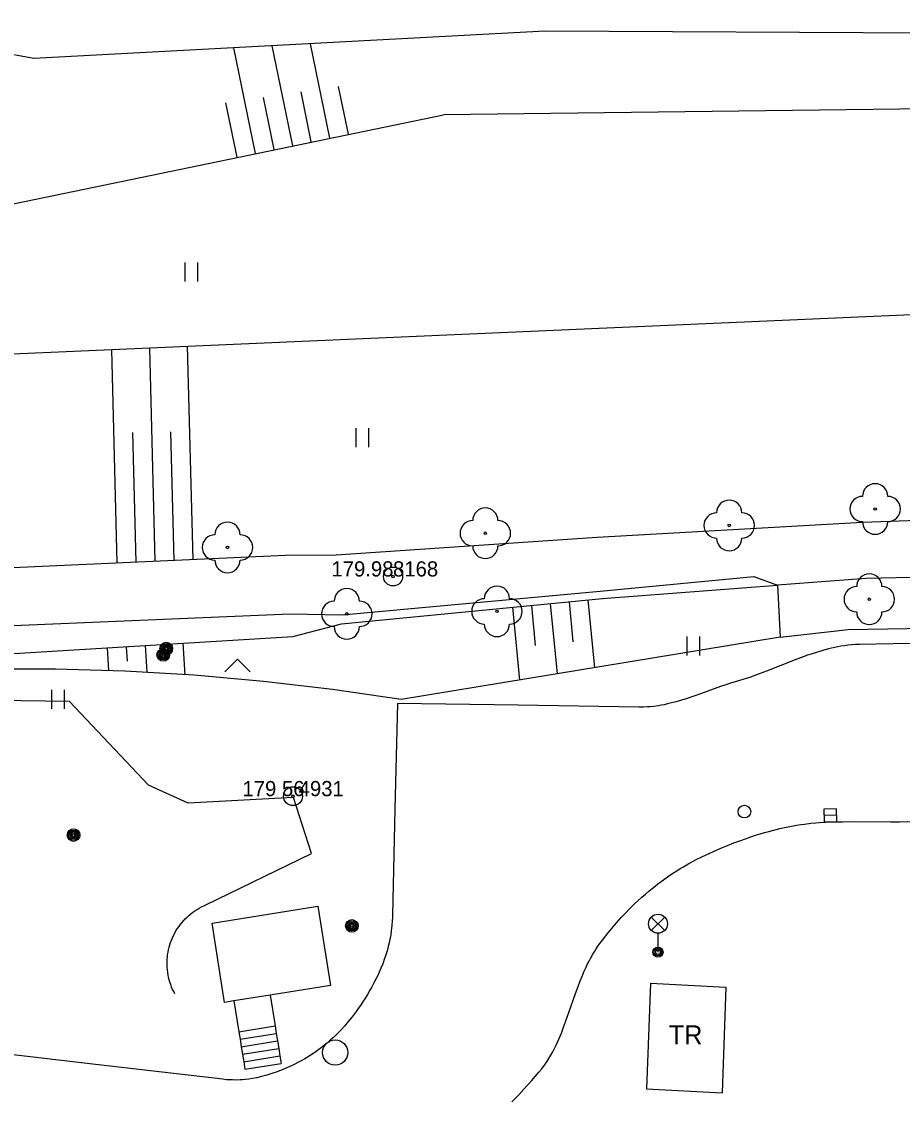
# Model space of a CAD drawing. Extents: x -538441 to -536770, y -1181008 to -1179809.
# Drawn here: x -537430.73 to -537395.89, y -1180815.56 to -1180772.89 of the extents above; entities that cross this region are included whole.
import ezdxf

# ---------------------------------------------------------------- set-up
doc = ezdxf.new("R2010")
doc.units = 0
for name, color, linetype in [('Vrstva 10', 7, 'Continuous'), ('Vrstva 11', 7, 'Continuous'), ('Vrstva 14', 7, 'Continuous'), ('Vrstva 15', 7, 'Continuous'), ('Vrstva 21', 7, 'Continuous'), ('Vrstva 22', 7, 'Continuous'), ('Vrstva 23', 7, 'Continuous'), ('Vrstva 25', 7, 'Continuous'), ('Vrstva 27', 7, 'Continuous'), ('Vrstva 28', 7, 'Continuous'), ('Vrstva 33', 7, 'Continuous'), ('Vrstva 36', 7, 'Continuous'), ('Vrstva 41', 7, 'Continuous'), ('Vrstva 5', 7, 'Continuous')]:
    doc.layers.add(name, color=color, linetype=linetype)

msp = doc.modelspace()

# ---------------------------------------------------------------- linework, layer by layer
at = {"layer": 'Vrstva 10'}
msp.add_line((-537392.278, -1180797.422), (-537397.59, -1180797.53), dxfattribs=at)
for points in [[(-537397.59, -1180797.53), (-537397.747, -1180797.536), (-537397.898, -1180797.546), (-537398.044, -1180797.561), (-537398.184, -1180797.579), (-537398.32, -1180797.6), (-537398.451, -1180797.624), (-537398.577, -1180797.649), (-537398.699, -1180797.676), (-537398.817, -1180797.705), (-537399.044, -1180797.766), (-537399.256, -1180797.829), (-537399.454, -1180797.893), (-537399.639, -1180797.956), (-537399.813, -1180798.018), (-537400.137, -1180798.14), (-537401.268, -1180798.588), (-537401.552, -1180798.695), (-537401.765, -1180798.773), (-537401.926, -1180798.829), (-537402.167, -1180798.908), (-537402.41, -1180798.98), (-537402.652, -1180799.052), (-537402.878, -1180799.125), (-537403.089, -1180799.197), (-537403.486, -1180799.338), (-537403.832, -1180799.464), (-537404.136, -1180799.571), (-537404.402, -1180799.661), (-537404.636, -1180799.735), (-537404.84, -1180799.795), (-537405.02, -1180799.843), (-537405.178, -1180799.881), (-537405.317, -1180799.911), (-537405.438, -1180799.934), (-537405.545, -1180799.953), (-537405.732, -1180799.979), (-537405.873, -1180799.994), (-537405.98, -1180800.002), (-537406.139, -1180800.009), (-537406.3, -1180800.01)], [(-537415.87, -1180799.86), (-537415.965, -1180804.05), (-537416.06, -1180808.24), (-537416.064, -1180808.349), (-537416.069, -1180808.454), (-537416.085, -1180808.656), (-537416.108, -1180808.843), (-537416.134, -1180809.018), (-537416.164, -1180809.182), (-537416.197, -1180809.334), (-537416.231, -1180809.476), (-537416.266, -1180809.608), (-537416.303, -1180809.732)], [(-537406.3, -1180800.01), (-537411.085, -1180799.935), (-537415.87, -1180799.86)], [(-537403.072, -1180805.589), (-537402.805, -1180805.478), (-537402.555, -1180805.379), (-537402.32, -1180805.29), (-537402.099, -1180805.211), (-537401.892, -1180805.14), (-537401.697, -1180805.076), (-537401.514, -1180805.019), (-537401.342, -1180804.969), (-537401.181, -1180804.924), (-537401.03, -1180804.884), (-537400.745, -1180804.814), (-537400.495, -1180804.759), (-537400.276, -1180804.716), (-537400.084, -1180804.682), (-537399.915, -1180804.655), (-537399.767, -1180804.634), (-537399.507, -1180804.603), (-537399.311, -1180804.583), (-537399.164, -1180804.572), (-537398.942, -1180804.558), (-537398.72, -1180804.55), (-537398.244, -1180804.541), (-537397.827, -1180804.538), (-537396.368, -1180804.54), (-537396.004, -1180804.539), (-537395.457, -1180804.534)], [(-537409.291, -1180812.672), (-537409.212, -1180812.457), (-537409.068, -1180812.049), (-537408.82, -1180811.33), (-537408.722, -1180811.061), (-537408.633, -1180810.828), (-537408.551, -1180810.625), (-537408.476, -1180810.45), (-537408.407, -1180810.298), (-537408.343, -1180810.166), (-537408.286, -1180810.052), (-537408.233, -1180809.953), (-537408.137, -1180809.782), (-537408.061, -1180809.656), (-537408.002, -1180809.563), (-537407.909, -1180809.425), (-537407.81, -1180809.29), (-537407.705, -1180809.153), (-537407.602, -1180809.021), (-537407.398, -1180808.772), (-537407.203, -1180808.543), (-537407.016, -1180808.334), (-537406.837, -1180808.143), (-537406.667, -1180807.968), (-537406.504, -1180807.807), (-537406.348, -1180807.66), (-537406.2, -1180807.525), (-537406.058, -1180807.401), (-537405.924, -1180807.286), (-537405.796, -1180807.181), (-537405.675, -1180807.085), (-537405.56, -1180806.996), (-537405.341, -1180806.833), (-537405.145, -1180806.695), (-537404.97, -1180806.578), (-537404.815, -1180806.478), (-537404.677, -1180806.392), (-537404.555, -1180806.319), (-537404.338, -1180806.195), (-537404.172, -1180806.105), (-537404.046, -1180806.039), (-537403.855, -1180805.943), (-537403.66, -1180805.85), (-537403.357, -1180805.713), (-537403.072, -1180805.589)], [(-537416.303, -1180809.732), (-537416.339, -1180809.847), (-537416.375, -1180809.955), (-537416.449, -1180810.157), (-537416.519, -1180810.333), (-537416.586, -1180810.486), (-537416.647, -1180810.62), (-537416.703, -1180810.737), (-537416.807, -1180810.941), (-537416.889, -1180811.094), (-537416.954, -1180811.208), (-537417.054, -1180811.379), (-537417.16, -1180811.55), (-537417.246, -1180811.683), (-537417.33, -1180811.809), (-537417.414, -1180811.929), (-537417.496, -1180812.043), (-537417.577, -1180812.152), (-537417.656, -1180812.255), (-537417.734, -1180812.353), (-537417.811, -1180812.446), (-537417.964, -1180812.622), (-537418.11, -1180812.781), (-537418.251, -1180812.925), (-537418.386, -1180813.056), (-537418.516, -1180813.174), (-537418.639, -1180813.282), (-537418.757, -1180813.379), (-537418.87, -1180813.468), (-537418.977, -1180813.549), (-537419.079, -1180813.623), (-537419.176, -1180813.691), (-537419.362, -1180813.812), (-537419.527, -1180813.914), (-537419.675, -1180813.999), (-537419.807, -1180814.07), (-537419.924, -1180814.13), (-537420.028, -1180814.181), (-537420.213, -1180814.266), (-537420.354, -1180814.326), (-537420.461, -1180814.369), (-537420.624, -1180814.431), (-537420.79, -1180814.49), (-537420.914, -1180814.531), (-537421.031, -1180814.566), (-537421.14, -1180814.596), (-537421.243, -1180814.622), (-537421.435, -1180814.666), (-537421.603, -1180814.697), (-537421.75, -1180814.719), (-537421.879, -1180814.734), (-537421.991, -1180814.744), (-537422.09, -1180814.751), (-537422.262, -1180814.757), (-537422.392, -1180814.756), (-537422.489, -1180814.753), (-537422.634, -1180814.744), (-537422.78, -1180814.73)], [(-537409.593, -1180813.384), (-537409.535, -1180813.26), (-537409.481, -1180813.138), (-537409.38, -1180812.899), (-537409.291, -1180812.672)], [(-537422.78, -1180814.73), (-537427.695, -1180814.155), (-537432.314, -1180813.615)], [(-537411.337, -1180815.626), (-537411.064, -1180815.337), (-537410.862, -1180815.119), (-537410.563, -1180814.787), (-537410.416, -1180814.619), (-537410.27, -1180814.45), (-537410.158, -1180814.312), (-537410.055, -1180814.175), (-537409.961, -1180814.039), (-537409.875, -1180813.904), (-537409.796, -1180813.771), (-537409.723, -1180813.64), (-537409.656, -1180813.511)], [(-537409.656, -1180813.511), (-537409.593, -1180813.384)]]:
    msp.add_lwpolyline(points, dxfattribs=at)
at = {"layer": 'Vrstva 11'}
for p, q in [((-537420.293, -1180794.008), (-537438.556, -1180794.829)), ((-537418.294, -1180793.996), (-537420.293, -1180794.008)), ((-537407.85, -1180795.415), (-537401.77, -1180794.843)), ((-537401.77, -1180794.843), (-537400.826, -1180795.182)), ((-537384.63, -1180794.687), (-537397.336, -1180794.914)), ((-537418.058, -1180796.359), (-537407.85, -1180795.415)), ((-537438.451, -1180797.087), (-537420.107, -1180796.322)), ((-537420.107, -1180796.322), (-537418.058, -1180796.359)), ((-537398.035, -1180796.942), (-537384.349, -1180796.71)), ((-537423.44, -1180807.83), (-537419.26, -1180805.8)), ((-537422.138, -1180812.847), (-537420.706, -1180812.618)), ((-537422.091, -1180813.144), (-537420.659, -1180812.915)), ((-537422.044, -1180813.44), (-537420.612, -1180813.211)), ((-537421.996, -1180813.736), (-537420.564, -1180813.507)), ((-537421.949, -1180814.032), (-537420.517, -1180813.803)), ((-537421.902, -1180814.329), (-537420.47, -1180814.1))]:
    msp.add_line(p, q, dxfattribs=at)
for points in [[(-537397.336, -1180794.914), (-537400.826, -1180795.182), (-537400.729, -1180797.245), (-537398.035, -1180796.942)], [(-537428.84, -1180799.78), (-537455.66, -1180799.41)], [(-537425.72, -1180803.1), (-537428.84, -1180799.78)], [(-537419.26, -1180805.8), (-537419.98, -1180803.58), (-537424.15, -1180803.8), (-537425.72, -1180803.1)], [(-537424.67, -1180811.35), (-537424.716, -1180811.261), (-537424.759, -1180811.171), (-537424.798, -1180811.079), (-537424.834, -1180810.985), (-537424.866, -1180810.89), (-537424.894, -1180810.794), (-537424.918, -1180810.696), (-537424.938, -1180810.598), (-537424.954, -1180810.499), (-537424.966, -1180810.4), (-537424.974, -1180810.3), (-537424.979, -1180810.2), (-537424.979, -1180810.1), (-537424.975, -1180810), (-537424.967, -1180809.9), (-537424.956, -1180809.801), (-537424.94, -1180809.702), (-537424.92, -1180809.603), (-537424.897, -1180809.506), (-537424.87, -1180809.41), (-537424.838, -1180809.315), (-537424.803, -1180809.221), (-537424.765, -1180809.128), (-537424.722, -1180809.038), (-537424.676, -1180808.949), (-537424.627, -1180808.861), (-537424.574, -1180808.776), (-537424.518, -1180808.694), (-537424.458, -1180808.613), (-537424.396, -1180808.535), (-537424.33, -1180808.459), (-537424.261, -1180808.386), (-537424.189, -1180808.316), (-537424.115, -1180808.249), (-537424.038, -1180808.185), (-537423.959, -1180808.124), (-537423.877, -1180808.066), (-537423.793, -1180808.012), (-537423.707, -1180807.961), (-537423.619, -1180807.913), (-537423.529, -1180807.869), (-537423.44, -1180807.83)], [(-537420.9, -1180811.401), (-537420.706, -1180812.618), (-537420.659, -1180812.915), (-537420.612, -1180813.211), (-537420.564, -1180813.507), (-537420.517, -1180813.803), (-537420.47, -1180814.1)], [(-537422.333, -1180811.63), (-537422.138, -1180812.847), (-537422.091, -1180813.144), (-537422.044, -1180813.44), (-537421.996, -1180813.736), (-537421.949, -1180814.032), (-537421.902, -1180814.329)]]:
    msp.add_lwpolyline(points, dxfattribs=at)
at = {"layer": 'Vrstva 14'}
for p, q in [((-537430.25, -1180774.35), (-537438.4, -1180772.89)), ((-537410.02, -1180773.27), (-537430.25, -1180774.35)), ((-537360.28, -1180773.52), (-537410.02, -1180773.27)), ((-537359.89, -1180775.91), (-537414.043, -1180776.576)), ((-537384.292, -1180792.272), (-537397.467, -1180792.701)), ((-537397.467, -1180792.701), (-537407.963, -1180793.297)), ((-537407.963, -1180793.297), (-537418.294, -1180793.996)), ((-537407.749, -1180795.711), (-537400.826, -1180795.182)), ((-537418.076, -1180796.71), (-537407.749, -1180795.711)), ((-537420.002, -1180797.217), (-537418.076, -1180796.71)), ((-537438.453, -1180798.344), (-537420.002, -1180797.217)), ((-537400.729, -1180797.245), (-537415.721, -1180799.709))]:
    msp.add_line(p, q, dxfattribs=at)
for points in [[(-537423.908, -1180798.749), (-537426.652, -1180798.588), (-537429.399, -1180798.508), (-537432.148, -1180798.507)], [(-537415.721, -1180799.709), (-537418.44, -1180799.31), (-537421.17, -1180798.99), (-537423.908, -1180798.749)]]:
    msp.add_lwpolyline(points, dxfattribs=at)
at = {"layer": 'Vrstva 15'}
for p, q in [((-537421.478, -1180778.105), (-537422.337, -1180773.928)), ((-537420.009, -1180777.803), (-537420.822, -1180773.847)), ((-537418.539, -1180777.501), (-537419.308, -1180773.766)), ((-537419.274, -1180777.652), (-537419.681, -1180775.672)), ((-537417.805, -1180777.35), (-537418.194, -1180775.456)), ((-537422.212, -1180778.256), (-537422.656, -1180776.103)), ((-537420.743, -1180777.954), (-537421.168, -1180775.887)), ((-537431.39, -1180780.16), (-537414.043, -1180776.576)), ((-537436.36, -1180786.268), (-537376.856, -1180783.663)), ((-537427.176, -1180785.866), (-537426.964, -1180794.308)), ((-537425.677, -1180785.8), (-537425.465, -1180794.241)), ((-537424.179, -1180785.735), (-537423.966, -1180794.173)), ((-537426.343, -1180789.15), (-537426.215, -1180794.274)), ((-537424.844, -1180789.112), (-537424.716, -1180794.207)), ((-537411.023, -1180798.937), (-537411.302, -1180796.055)), ((-537410.402, -1180797.57), (-537410.555, -1180795.982)), ((-537409.54, -1180798.693), (-537409.809, -1180795.91)), ((-537408.909, -1180797.425), (-537409.062, -1180795.838)), ((-537408.056, -1180798.449), (-537408.316, -1180795.766)), ((-537427.28, -1180798.563), (-537427.335, -1180797.665)), ((-537426.551, -1180798.194), (-537426.586, -1180797.619)), ((-537425.773, -1180798.631), (-537425.837, -1180797.573)), ((-537425.054, -1180798.103), (-537425.089, -1180797.528)), ((-537424.264, -1180798.724), (-537424.34, -1180797.482))]:
    msp.add_line(p, q, dxfattribs=at)
at = {"layer": 'Vrstva 21'}
for centre, radius in [((-537416.04, -1180794.84), 0.375), ((-537416.04, -1180794.84), 0.375), ((-537416.04, -1180794.84), 0.05), ((-537416.04, -1180794.84), 0.05), ((-537419.997, -1180803.53), 0.375), ((-537419.997, -1180803.53), 0.05)]:
    msp.add_circle(centre, radius, dxfattribs=at)
at = {"layer": 'Vrstva 22'}
for centre in [(-537396.97, -1180792.17), (-537412.39, -1180793.13), (-537402.74, -1180792.82), (-537422.59, -1180793.69), (-537397.2, -1180795.74), (-537417.87, -1180796.32), (-537411.93, -1180796.22)]:
    msp.add_circle(centre, 0.05, dxfattribs=at)
for centre, start, end in [((-537396.97, -1180791.67), 0, 180), ((-537402.74, -1180792.32), 0, 180), ((-537397.47, -1180792.17), 90, 270), ((-537396.47, -1180792.17), 270, 90), ((-537412.39, -1180792.63), 0, 180), ((-537422.59, -1180793.19), 0, 180), ((-537412.89, -1180793.13), 90, 270), ((-537411.89, -1180793.13), 270, 90), ((-537403.24, -1180792.82), 90, 270), ((-537402.24, -1180792.82), 270, 90), ((-537396.97, -1180792.67), 180, 0), ((-537423.09, -1180793.69), 90, 270), ((-537422.09, -1180793.69), 270, 90), ((-537402.74, -1180793.32), 180, 0), ((-537412.39, -1180793.63), 180, 0), ((-537422.59, -1180794.19), 180, 0), ((-537397.2, -1180795.24), 0, 180), ((-537411.93, -1180795.72), 0, 180), ((-537397.7, -1180795.74), 90, 270), ((-537396.7, -1180795.74), 270, 90), ((-537417.87, -1180795.82), 0, 180), ((-537412.43, -1180796.22), 90, 270), ((-537411.43, -1180796.22), 270, 90), ((-537418.37, -1180796.32), 90, 270), ((-537417.37, -1180796.32), 270, 90), ((-537397.2, -1180796.24), 180, 0), ((-537417.87, -1180796.82), 180, 0), ((-537411.93, -1180796.72), 180, 0)]:
    msp.add_arc(centre, 0.5, start, end, dxfattribs=at)
at = {"layer": 'Vrstva 25'}
for centre, radius in [((-537425.01, -1180797.69), 0.25), ((-537425.13, -1180797.94), 0.25), ((-537425.13, -1180797.94), 0.2), ((-537425.13, -1180797.94), 0.15), ((-537425.13, -1180797.94), 0.1), ((-537425.01, -1180797.69), 0.2), ((-537425.01, -1180797.69), 0.15), ((-537425.01, -1180797.69), 0.1), ((-537425.01, -1180797.69), 0.05), ((-537425.13, -1180797.94), 0.05), ((-537428.68, -1180805.07), 0.25), ((-537428.68, -1180805.07), 0.2), ((-537428.68, -1180805.07), 0.15), ((-537428.68, -1180805.07), 0.1), ((-537428.68, -1180805.07), 0.05), ((-537417.67, -1180808.66), 0.25), ((-537417.67, -1180808.66), 0.2), ((-537417.67, -1180808.66), 0.15), ((-537417.67, -1180808.66), 0.1), ((-537417.67, -1180808.66), 0.05)]:
    msp.add_circle(centre, radius, dxfattribs=at)
at = {"layer": 'Vrstva 27'}
msp.add_line((-537398.488, -1180804.277), (-537398.988, -1180804.291), dxfattribs=at)
msp.add_lwpolyline([(-537398.495, -1180804.027), (-537398.995, -1180804.041), (-537398.981, -1180804.541), (-537398.481, -1180804.527)], close=True, dxfattribs=at)
msp.add_circle((-537418.33, -1180813.67), 0.5, dxfattribs=at)
at = {"layer": 'Vrstva 28'}
msp.add_circle((-537402.14, -1180804.14), 0.25, dxfattribs=at)
at = {"layer": 'Vrstva 33'}
for p, q in [((-537405.825, -1180808.84), (-537405.295, -1180808.31)), ((-537405.825, -1180808.31), (-537405.295, -1180808.84)), ((-537405.56, -1180808.95), (-537405.56, -1180809.7))]:
    msp.add_line(p, q, dxfattribs=at)
for centre, radius in [((-537405.56, -1180808.575), 0.375), ((-537405.56, -1180809.7), 0.2), ((-537405.56, -1180809.7), 0.145), ((-537405.56, -1180809.7), 0.0876)]:
    msp.add_circle(centre, radius, dxfattribs=at)
at = {"layer": 'Vrstva 36'}
for p, q in [((-537424.257, -1180783.166), (-537424.257, -1180782.416)), ((-537423.757, -1180783.166), (-537423.757, -1180782.416)), ((-537417.497, -1180789.72), (-537417.497, -1180788.97)), ((-537416.997, -1180789.72), (-537416.997, -1180788.97)), ((-537404.4, -1180797.965), (-537404.4, -1180797.215)), ((-537403.9, -1180797.965), (-537403.9, -1180797.215)), ((-537429.538, -1180800.079), (-537429.538, -1180799.329)), ((-537429.038, -1180800.079), (-537429.038, -1180799.329))]:
    msp.add_line(p, q, dxfattribs=at)
msp.add_lwpolyline([(-537422.691, -1180798.605), (-537422.191, -1180798.105), (-537421.691, -1180798.605)], dxfattribs=at)
at = {"layer": 'Vrstva 5'}
for p, q in [((-537423.2, -1180808.55), (-537419.011, -1180807.882)), ((-537419.011, -1180807.882), (-537418.51, -1180811.02)), ((-537422.71, -1180811.69), (-537423.2, -1180808.55)), ((-537405.855, -1180810.927), (-537406.009, -1180815.106)), ((-537405.855, -1180810.927), (-537402.87, -1180811.08)), ((-537402.87, -1180811.08), (-537403.024, -1180815.259)), ((-537406.009, -1180815.106), (-537403.024, -1180815.259))]:
    msp.add_line(p, q, dxfattribs=at)
for points in [[(-537418.51, -1180811.02), (-537420.9, -1180811.401)], [(-537420.9, -1180811.401), (-537422.333, -1180811.63)], [(-537422.333, -1180811.63), (-537422.71, -1180811.69)]]:
    msp.add_lwpolyline(points, dxfattribs=at)

# ---------------------------------------------------------------- texts
at = {"layer": 'Vrstva 22'}
for s, p in [('179.98 ', (-537418.477, -1180794.84)), ('179 56 ', (-537421.997, -1180803.53))]:
    msp.add_text(s, height=0.6, dxfattribs=at).set_placement(p)
at = {"layer": 'Vrstva 23'}
for s, p in [('8168', (-537416.04, -1180794.84)), (' 4931', (-537419.997, -1180803.53))]:
    msp.add_text(s, height=0.6, dxfattribs=at).set_placement(p)
at = {"layer": 'Vrstva 41'}
msp.add_text('TR', height=0.75, dxfattribs=at).set_placement((-537405.139, -1180813.346))

doc.saveas('drawing.dxf')
